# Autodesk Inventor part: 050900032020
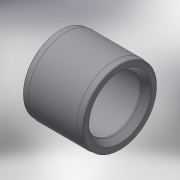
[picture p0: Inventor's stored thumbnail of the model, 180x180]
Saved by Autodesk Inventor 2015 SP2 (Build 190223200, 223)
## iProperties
Created: 2017-11
Part Number: 050900032020
Material: Generic
Description: PLASSON BUSHING-CEMENT PVC 32-20
Document SubType Name: Modeling
Designer: KIM
Density: 1 g/cm^3
Appearance: Default
Author: KIM
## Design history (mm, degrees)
derived "050900.ipt"
feature "Solid1::050900.ipt"
tag "TaggingFeature1"
body "Solid1"
other parameters: "d1" = 32, "d2" = 16, "d3" = 22, "d7" = 2.2, "d11" = 2.2, "d12" = 0.32, "d14" = 0.32, "d15" = 2.2, "d17" = 0.32, "d18" = 0.32, "d19" = 17.8, "d20" = 1.2, "d21" = 4.26, "D_" = 32, "L_" = 22, "l_" = 16, "z_" = 2
